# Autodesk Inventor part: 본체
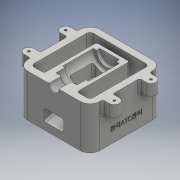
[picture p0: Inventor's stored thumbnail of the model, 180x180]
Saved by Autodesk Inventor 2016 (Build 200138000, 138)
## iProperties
Created: 2018-01
Part Number: 본체
Material: 일반
Document SubType Name: Modeling
Designer: 605-15
Density: 1 g/cm^3
Appearance: 기본값
Author: 605-15
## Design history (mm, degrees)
sketch "스케치1"
  geometry: L1 (-55, 55)-(55, 55); L2 (55, 55)-(55, -55); L3 (55, -55)-(-55, -55); L4 (-55, -55)-(-55, 55); L5 (-55, 55)-(55, -55); 2 further points
  constraints: 10 end point, 2 parallel, 1 coincident, 1 horizontal, 1 midpoint, 1 perpendicular
  dimensions: "d0" = 110 distance of L2.end L3.end; "d1" = 110 distance of L1.end L2.end
extrude "돌출1" new body sketch "스케치1" distance "d2" = 65; taper "d3" = 0 deg
sketch "스케치2"
  geometry: L1 (-45, 45)-(-45, -45); L2 (-45, -45)-(-25, -45); L3 (-25, -45)-(-25, 35); L4 (-25, 35)-(0, 35); L5 (-45, 45)-(0, 45); L6 (55, 55)-(-55, 55) reference; L7 (0, 55)-(0, -55); L8 (-55, -55)-(55, -55) reference; L9 (-55, 55)-(-55, -55) reference; L10 (-55, 0)-(55, 0); L11 (55, -55)-(55, 55) reference; L12 (45, 45)-(45, -45); L13 (25, -45)-(25, 35); L14 (25, 35)-(0, 35); L15 (45, 45)-(0, 45); L16 (45, -45)-(25, -45); 1 further point
  constraints: 24 end point, 4 midpoint, 4 symmetric about line, 3 perpendicular, 1 horizontal, 1 vertical
  dimensions: "d4" = 10 distance between parallel lines of L15 L6; "d5" = 20 distance between parallel lines of L14 L6; "d6" = 10 distance between parallel lines of L1 L9; "d7" = 30 distance between parallel lines of L3 L9; "d8" = 10 distance between parallel lines of L8 L2
extrude "돌출2" cut sketch "스케치2" stored distance "d9" = 10; taper "d10" = 0 deg
sketch "스케치3"
  geometry: L1 (-55, 55)-(-55, -55) reference; L2 (-55, -55)-(-55, 55) reference; L3 (-55, -20.5)-(-65, -20.5); L4 (-65, -35.5)-(-55, -35.5); L5 (-55, -55)-(55, -55) reference; A1 r 7.5 centre (-65, -28) between (-65, -20.5) and (-65, -35.5); 1 further point
  constraints: 4 end point, 2 perpendicular, 2 point on circle, 2 point on line, 2 tangent, 1 centre point
  dimensions: "d11" = 10 distance from line of L1 A1.centre; "d12" = 27 distance from line of L5 A1.centre; "d13" = 7.5 radius of A1
extrude "돌출3" join sketch "스케치3" distance "d14" = 20; taper "d15" = 0 deg
sketch "스케치4"
  geometry: L1 (-55, 57.5)-(-36, 57.5); L2 (-36, 49)-(-22, 49); L3 (-22, 45)-(25, 45); L4 (25, 50)-(30, 50); L5 (35, 65)-(-45, 65) reference; L6 (-55, 0)-(-55, 65) reference; L7 (-55, 65)-(-55, 57.5); L8 (-36, 57.5)-(-36, 49); L9 (-35.5, 65)-(-35.5, 45) reference; L10 (-22, 49)-(-22, 45); L11 (25, 45)-(25, 50); L12 (20.5, 45)-(35.5, 45) reference; L13 (30, 50)-(30, 65); L14 (-35.5, 65)-(-55, 65) reference; L15 (-55, 65)-(30, 65); L16 (20.5, 65)-(35.5, 65) reference; 1 further point
  constraints: 20 end point, 4 horizontal, 2 collinear, 2 parallel, 2 perpendicular, 1 point on line
  dimensions: "d16" = 19 distance of L1.start L1.end; "d17" = 14 distance of L2.start L2.end; "d18" = 47 distance of L3.start L3.end; "d19" = 5 distance of L4.start L4.end; "d20" = 15 diameter of L1 L5; "d21" = 32 diameter of L2 L5; "d22" = 40 diameter of L3 L5; "d23" = 30 diameter of L4 L5
revolve "회전1" sketch "스케치4" stored, may be unused: angle "d24" = 90 deg
sketch "스케치5"
  geometry: L1 (-22, 45)-(25, 45) reference; L2 (-17, 45)-(-17, 39.243); L3 (-17, 39.243)-(-55, 29.061); L4 (-55, 0)-(-55, 65) reference; L5 (20, 45)-(20, 31.157); L6 (20, 31.157)-(-55, 11.061); L7 (-45, 8.564)-(35, 30); L8 (-45, 8.564)-(-45, 0); L9 (-45, 0)-(35, 0) reference; L10 (45, 65)-(45, 0) reference; L11 (1.5, 45)-(1.5, 67.162); L12 (-45, 0)-(35, 0); L13 (35, 65)-(35, 0) reference; L14 (35, 30)-(35, 0); 1 further point
  constraints: 18 end point, 4 point on line, 4 vertical, 2 collinear, 1 midpoint, 1 parallel, 1 vertical alignment, 1 other
  dimensions: "d25" = 75 deg angle of L3 L4; "d26" = 37 distance between parallel lines of L5 L2; "d27" = 18 distance of L6.end L3.end; "d28" = 5 distance between parallel lines of L7 L6; "d29" = 30 distance from line of L7.end L9
extrude "돌출4" cut sketch "스케치5" stored distance "d31" = 30; taper "d32" = 0 deg
extrude "돌출5" cut sketch "스케치5" stored distance "d33" = 50; taper "d34" = 0 deg
node "작업 평면1"
sketch "스케치6"
  geometry: L1 (40, 38)-(70, 38); L2 (70, 38)-(70, 75); L3 (70, 75)-(40, 75); L4 (40, 75)-(40, 38); L5 (40, 38)-(70, 75); L6 (35, 80)-(40, 80) reference; L7 (40, 80)-(40, 85) reference; 1 further point
  constraints: 10 end point, 2 parallel, 1 collinear, 1 horizontal, 1 perpendicular
  dimensions: "d35" = 30 distance of L3.end L2.end; "d36" = 37 distance of L2.end L1.end; "d37" = 5 distance between parallel lines of L6 L3
extrude "돌출6" cut sketch "스케치6" stored distance "d38" = 0; taper "d39" = 0 deg
hole "구멍1" diameter "d42" = 3.459; stored, may be unused: countersink angle "d46" = 90 deg, drill point angle "d48" = 118 deg; dims "d43" = 9, "d44" = 4, "d45" = 2, "d47" = 11, "d63" = 10, "d64" = 10
sketch "스케치7" dims "d65" = 3
  geometry: L1 (-23.602, 30.113)-(-23.602, 79.887); L2 (-23.602, 79.887)-(-16.398, 79.887); L3 (-16.398, 79.887)-(-16.398, 30.113); L4 (-16.398, 30.113)-(-23.602, 30.113); L5 (-23.602, 30.113)-(-16.398, 79.887); L6 (0, 110)-(0, 0) reference; 3 further points
  constraints: 2 end point, 2 midpoint, 1 horizontal alignment, 2 other
  dimensions: "d49" = 20 distance of point (0, 55) point (-20, 55)
feature "엠보싱1" sketch "스케치7" dims "d0" = 110, "d1" = 110, "d4" = 10, "d5" = 20, "d6" = 10, "d7" = 30, "d8" = 10, "d50" = 0.5, "d51" = 0
fillet "모깎기1" dims "d52" = 5
fillet "모깎기2" dims "d53" = 15
fillet "모깎기3" dims "d54" = 3
fillet "모깎기4" dims "d55" = 3
fillet "모깎기5" dims "d56" = 3
fillet "모깎기6" dims "d57" = 3
fillet "모깎기7" dims "d58" = 3
chamfer "모따기1" distance "d59" = 1; stored, may be unused: second distance "d60" = 2, angle "d61" = 45 deg
fillet "모깎기8" dims "d62" = 1
fillet "모깎기9" dims "d65" = 3
node "솔리드1"
mirror "대칭1"
mirror "대칭2"
mirror "대칭3"
mirror "대칭4"
